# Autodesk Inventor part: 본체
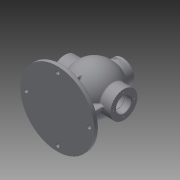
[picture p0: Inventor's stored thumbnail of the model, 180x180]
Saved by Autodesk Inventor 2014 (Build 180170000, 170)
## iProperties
Created: 2020-08
Part Number: 본체
Material: Generic
Document SubType Name: Modeling
Designer: kh
Density: 1 g/cm^3
Appearance: Default
Author: kh
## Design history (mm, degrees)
sketch "Sketch1"
  geometry: L1 (-53, 85)-(53, 85); A1 r 53 centre (0, 85) between (53, 85) and (-53, 85); 2 further points
  constraints: 2 end point, 2 horizontal alignment, 2 point on circle, 1 centre point, 1 midpoint, 1 vertical alignment
  dimensions: "d0" = 106 diameter of A1; "d1" = 85 distance of point (0, 0) A1.centre
revolve "Revolution1" sketch "Sketch1" stored, may be unused: angle "d2" = 90 deg
shell "Shell1" dims "d3" = 10
sketch "Sketch2"
  geometry: C1 r 85 at (0, 0); 1 further point
  constraints: 1 centre point, 1 coincident
  dimensions: "d4" = 170 diameter of C1
extrude "Extrusion1" join sketch "Sketch2" distance "d5" = 10; taper "d6" = 0 deg
workplane "Work Plane1"
sketch "Sketch3"
  geometry: C1 r 31 at (85, 0); 1 further point
  constraints: 1 centre point, 1 horizontal alignment
  dimensions: "d8" = 62 diameter of C1; "d9" = 85 distance of C1.centre point (0, 0)
extrude "Extrusion2" join sketch "Sketch3" stored distance "d10" = 10; taper "d11" = 0 deg
sketch "Sketch4"
  geometry: C1 r 31 at (0, 0) reference; C2 r 17.5 at (0, 0); 1 further point
  constraints: 1 centre point, 1 coincident
  dimensions: "d12" = 35 diameter of C2
extrude "Extrusion3" cut sketch "Sketch4" stored distance "d13" = 10; taper "d14" = 0 deg
sketch "Sketch5" dims "d15" = 48
  geometry: L1 (0, 0)-(0, 24); C1 r 31 at (0, 0) reference; 2 further points
  constraints: 2 coincident, 2 end point, 1 vertical, 1 vertical alignment, 2 other
hole "Hole1" sketch "Sketch5" at (0, 24) diameter "d16" = 3.242; stored, may be unused: countersink angle "d20" = 90 deg, drill point angle "d22" = 118 deg; dims "d17" = 12, "d18" = 4, "d19" = 2, "d21" = 15
pattern_circular "Circular Pattern1" dims angle "d24" = 360 deg
mirror "Mirror1"
workplane "Work Plane2"
sketch "Sketch6"
  geometry: C1 r 27 at (0, 0); 1 further point
  constraints: 1 centre point, 1 coincident
  dimensions: "d27" = 54 diameter of C1
extrude "Extrusion4" join sketch "Sketch6" stored distance "d28" = 10; taper "d29" = 0 deg
sketch "Sketch7"
  geometry: C1 r 13 at (0, 0); 1 further point
  constraints: 1 centre point, 1 coincident
  dimensions: "d30" = 26 diameter of C1
extrude "Extrusion5" cut sketch "Sketch7" stored distance "d31" = 10; taper "d32" = 0 deg
sketch "Sketch8" dims "d33" = 40
  geometry: L1 (0, 0)-(0, 20); C1 r 27 at (0, 0) reference; 2 further points
  constraints: 2 coincident, 2 end point, 1 vertical, 1 vertical alignment, 2 other
hole "Hole2" sketch "Sketch8" at (0, 20) diameter "d34" = 3.242; stored, may be unused: countersink angle "d38" = 90 deg, drill point angle "d40" = 118 deg; dims "d35" = 12, "d36" = 4, "d37" = 2, "d39" = 15
pattern_circular "Circular Pattern2" dims angle "d42" = 360 deg
workplane "Work Plane3"
sketch "Sketch9"
  geometry: C1 r 17.5 at (0, 0) reference; C2 r 18.5 at (0, 0); 1 further point
  constraints: 1 centre point, 1 coincident
  dimensions: "d45" = 37 diameter of C2
extrude "Extrusion6" cut sketch "Sketch9" distance "d46" = 1.75; taper "d47" = 0 deg
sketch "Sketch10"
  geometry: L1 (-52, 4)-(52, 4); L2 (52, 4)-(52, -4); L3 (52, -4)-(-52, -4); L4 (-52, -4)-(-52, 4); L5 (-4, 43)-(4, 43); L6 (4, 43)-(4, -43); L7 (4, -43)-(-4, -43); L8 (-4, -43)-(-4, 43); L9 (-52, 0)-(52, 0); L10 (0, 43)-(0, -43); 2 further points
  constraints: 20 end point, 6 midpoint, 4 parallel, 2 horizontal, 2 perpendicular, 1 coincident
  dimensions: "d48" = 104 distance of L2.end L3.end; "d49" = 86 distance of L5.end L6.end; "d50" = 8 distance of L3.end L1.start; "d51" = 8 distance of L5.start L5.end
extrude "Extrusion7" join sketch "Sketch10" stored distance "d52" = 1.75; taper "d53" = 0 deg
workplane "Work Plane4"
sketch "Sketch11"
  geometry: L1 (-27, 150)-(27, 150) reference; 2 further points
  constraints: 1 vertical alignment, 1 other
  dimensions: "d55" = 9 distance from line of point (0, 141) L1
emboss "Emboss1" sketch "Sketch11" dims "d0" = 106, "d1" = 85, "d12" = 35, "d56" = 0.5, "d57" = 0
sketch "Sketch12"
  geometry: L1 (-72.5, 0)-(72.5, 0); L2 (0, 72.5)-(0, -72.5); C1 r 4.5 at (-72.5, 0); C2 r 4.5 at (0, 72.5); C3 r 4.5 at (72.5, 0); C4 r 4.5 at (0, -72.5); A1 r 72.5 centre (0, 0) between (-72.5, 0) and (72.5, 0); 2 further points
  constraints: 6 coincident, 5 centre point, 4 end point, 4 point on circle, 3 equal radius, 2 midpoint, 1 horizontal, 1 perpendicular
  dimensions: "d58" = 145 diameter of A1; "d59" = 9 diameter of C1
extrude "Extrusion8" cut sketch "Sketch12" stored distance "d60" = 0; taper "d61" = 0 deg
chamfer "Chamfer1" distance "d62" = 1; stored, may be unused: second distance "d63" = 2, angle "d64" = 45 deg
fillet "Fillet1" dims "d65" = 3, "d66" = 3
fillet "Fillet2" dims "d67" = 3
body "Solid1"
other parameters: "d7" = 68, "d54" = 261.25
